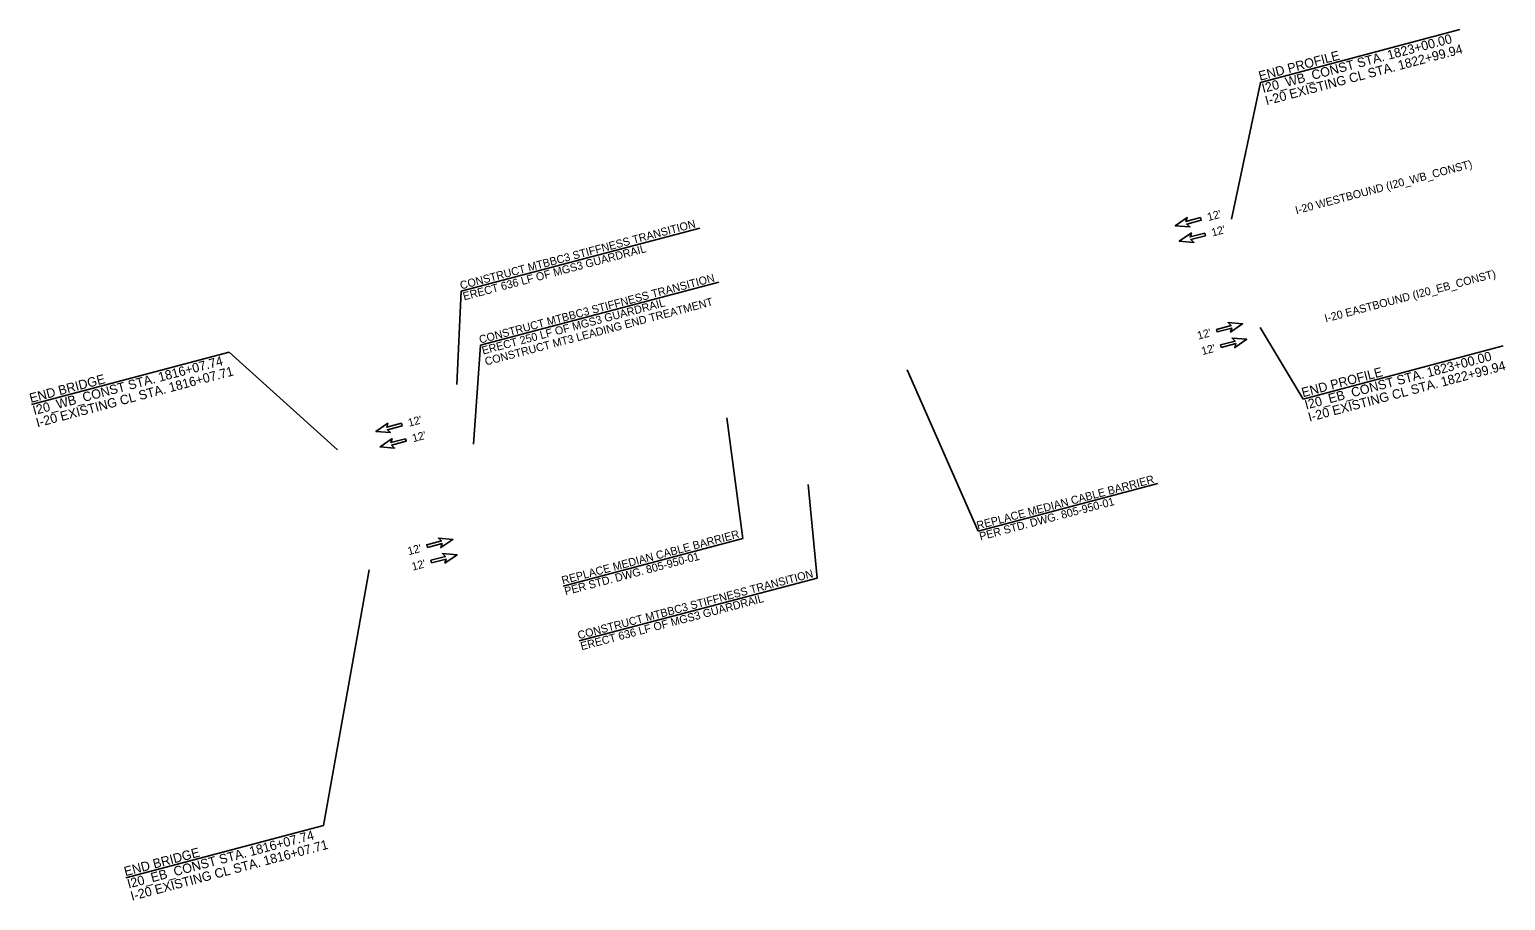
# Model space of a CAD drawing. Extents: x 2110155 to 2114862, y 866944 to 868497.
# Drawn here: x 2112437 to 2113543, y 867547 to 868200 of the extents above; entities that cross this region are included whole.
import ezdxf

# ---------------------------------------------------------------- set-up
doc = ezdxf.new("R2010")
doc.units = 0
doc.layers.add('RD_SHT_Bndy', color=7, linetype='Continuous')

msp = doc.modelspace()

# ---------------------------------------------------------------- linework, layer by layer
at = {"layer": 'RD_SHT_Bndy'}
for p, q in [((2113509.2, 868199.5), (2113359.6, 868159.9)), ((2112939.3, 868050.7), (2112760.5, 868003.4)), ((2112953.5, 868010.1), (2112774.8, 867962.8)), ((2113541.6, 867962.3), (2113391.7, 867922.5)), ((2112586.4, 867957.7), (2112438.2, 867918.4)), ((2113282.6, 867859.1), (2113148, 867823.4)), ((2112971.5, 867818), (2112836.8, 867782.3)), ((2113027.2, 867788.3), (2112848.9, 867741.1)), ((2112657.3, 867602.8), (2112509, 867563.5))]:
    msp.add_line(p, q, dxfattribs=at)
for points in [[(2113359.6, 868159.9), (2113337.9, 868057.4)], [(2112760.5, 868003.4), (2112757.1, 867933.4)], [(2113391.7, 867922.5), (2113359.4, 867976.2)], [(2112774.8, 867962.8), (2112769.6, 867888.6)], [(2112586.4, 867957.7), (2112667.6, 867884.4)], [(2113148, 867823.4), (2113094.7, 867944.4)], [(2112971.5, 867818), (2112959.6, 867908.3)], [(2113027.2, 867788.3), (2113020.6, 867858.4)], [(2112657.3, 867602.8), (2112691.4, 867794.5)]]:
    msp.add_lwpolyline(points, dxfattribs=at)
for points in [[(2113314.8, 868058.5), (2113315.3, 868056.5), (2113304.4, 868053.6), (2113306.7, 868051.5), (2113295.7, 868052.4), (2113304.8, 868058.6), (2113303.8, 868055.6)], [(2113317.9, 868046.9), (2113318.4, 868044.9), (2113307.4, 868042), (2113309.7, 868039.9), (2113298.8, 868040.8), (2113307.9, 868047), (2113306.9, 868044)], [(2113327.2, 867972.8), (2113326.7, 867974.7), (2113337.6, 867977.6), (2113335.3, 867979.8), (2113346.2, 867978.9), (2113337.2, 867972.7), (2113338.1, 867975.7)], [(2113330.2, 867961.2), (2113329.7, 867963.1), (2113340.7, 867966), (2113338.4, 867968.2), (2113349.3, 867967.3), (2113340.3, 867961.1), (2113341.2, 867964.1)], [(2112715.6, 867904.3), (2112716.1, 867902.4), (2112705.1, 867899.5), (2112707.4, 867897.3), (2112696.5, 867898.2), (2112705.5, 867904.4), (2112704.6, 867901.4)], [(2112718.6, 867892.7), (2112719.2, 867890.8), (2112708.2, 867887.9), (2112710.5, 867885.7), (2112699.6, 867886.6), (2112708.6, 867892.8), (2112707.7, 867889.8)], [(2112735.1, 867811.2), (2112734.6, 867813.2), (2112745.6, 867816.1), (2112743.3, 867818.2), (2112754.2, 867817.3), (2112745.1, 867811.1), (2112746.1, 867814.1)], [(2112738.2, 867799.6), (2112737.7, 867801.6), (2112748.6, 867804.5), (2112746.3, 867806.6), (2112757.3, 867805.7), (2112748.2, 867799.5), (2112749.1, 867802.5)]]:
    msp.add_lwpolyline(points, close=True, dxfattribs=at)

# ---------------------------------------------------------------- texts
for s, height, p in [('I20_WB_CONST STA. 1823+00.00', 7, (2113361.7, 868151.9)), ('END PROFILE', 7, (2113359.3, 868161.1)), ('I-20 EXISTING CL STA. 1822+99.94', 7, (2113364.2, 868142.7)), ('I-20 WESTBOUND (I20_WB_CONST)', 6, (2113386.6, 868061)), ("12'", 6, (2113320.6, 868055.9)), ('CONSTRUCT MTBBC3 STIFFNESS TRANSITION', 6, (2112760.4, 868004.6)), ("12'", 6, (2113323.7, 868044.3)), ('ERECT 636 LF OF MGS3 GUARDRAIL', 6, (2112762.6, 867996.4)), ('I-20 EASTBOUND (I20_EB_CONST)', 6, (2113408.6, 867979.9)), ('CONSTRUCT MTBBC3 STIFFNESS TRANSITION', 6, (2112774.7, 867964)), ('ERECT 250 LF OF MGS3 GUARDRAIL', 6, (2112776.8, 867955.8)), ('CONSTRUCT MT3 LEADING END TREATMENT', 6, (2112779, 867947.6)), ("12'", 6, (2113313.1, 867967)), ("12'", 6, (2113316.2, 867955.4)), ('I20_WB_CONST STA. 1816+07.74', 7, (2112440.3, 867910.4)), ('I20_EB_CONST STA. 1823+00.00', 7, (2113393.9, 867914.6)), ('I-20 EXISTING CL STA. 1822+99.94', 7, (2113396.4, 867905.4)), ('END BRIDGE', 7, (2112437.8, 867919.6)), ('I-20 EXISTING CL STA. 1816+07.71', 7, (2112442.7, 867901.2)), ('END PROFILE', 7, (2113391.5, 867923.8)), ("12'", 6, (2112721.4, 867901.7)), ("12'", 6, (2112724.5, 867890.1)), ('REPLACE MEDIAN CABLE BARRIER', 6, (2113147.7, 867824.6)), ('PER STD. DWG. 805-950-01', 6, (2113149.8, 867816.4)), ('REPLACE MEDIAN CABLE BARRIER', 6, (2112836.6, 867783.5)), ("12'", 6, (2112721.1, 867805.4)), ('PER STD. DWG. 805-950-01', 6, (2112838.7, 867775.3)), ("12'", 6, (2112724.2, 867793.8)), ('CONSTRUCT MTBBC3 STIFFNESS TRANSITION', 6, (2112848.6, 867742.3)), ('ERECT 636 LF OF MGS3 GUARDRAIL', 6, (2112850.7, 867734.1)), ('I20_EB_CONST STA. 1816+07.74', 7, (2112511.1, 867555.5)), ('END BRIDGE', 7, (2112508.7, 867564.7)), ('I-20 EXISTING CL STA. 1816+07.71', 7, (2112513.6, 867546.3))]:
    msp.add_text(s, height=height, rotation=14.8448, dxfattribs=at).set_placement(p)

doc.saveas('drawing.dxf')
